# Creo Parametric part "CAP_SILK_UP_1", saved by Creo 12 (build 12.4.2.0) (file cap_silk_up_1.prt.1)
Units: Custom; MM, KILOGRAM, SECS

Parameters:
  PTC_WM_ITERATION = "0"
  PTC_WM_VERSION = "-.0"
  PTC_WM_LIFECYCLE_STATE = "In Work"
  PTC_WM_LIFECYCLE = "MO_CADDocument"
  PTC_WM_CREATED_BY = "Maximilian Roepper (Z0017RMS: MO)"
  PTC_WM_CREATED_ON = "18-Sep-26 11:36:42 AM"
  PTC_WM_MODIFIED_BY = "Maximilian Roepper (Z0017RMS: MO)"
  PTC_WM_MODIFIED_ON = "18-Sep-26 11:36:46 AM"
  PDMLINKNUMBER = "PDM000071455130"
  PTC_WM_NAME = "cap_silk_up_1.prt"
  PTC_WM_NUMBER = "PDM000071455130"

Other parameters: WEIGHT, WEIGHT_FACTOR, WEIGHT_ADD, _MASS_TEMP, _DIFF_TEMP, MC_ERRORS, SUPPLIER

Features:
  1. coordinate system
  2. datum plane "PRT_YZ"
  3. datum plane "PRT_XY"
  4. datum plane "PRT_XZ"
  5. coordinate system
  6. datum axis
  7. datum axis
  8. datum axis
  9. coordinate system
  10. imported feature

Other named items: PRT, SIEMENS_MO, DRW_VIEW_ORG, PRT_X, PRT_Y, PRT_Z, CS0, ROUGH_GROB

Layers: 00_STD_CSYS-KSYS, 01_STD_PLANES-EBENEN, 02_STD_AXES-ACHSEN, 03_STD_CSYS-KSYS, 24_IMPORT_FEAT-IMPORT_KE

Surfaces: 10 plane, 4 cylinder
